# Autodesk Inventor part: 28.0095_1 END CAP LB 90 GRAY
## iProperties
Created: 2007-01
Part Number: 28.0095_1 END CAP LB 90 GRAY
Document SubType Name: Modeling
Designer: Andy Moles
Material: ABS Plastic
Density: 1.06 g/cm^3
Author: Andy Moles
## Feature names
1. Extrusion1
2. Fillet1
3. Fillet2
4. Extrusion2
